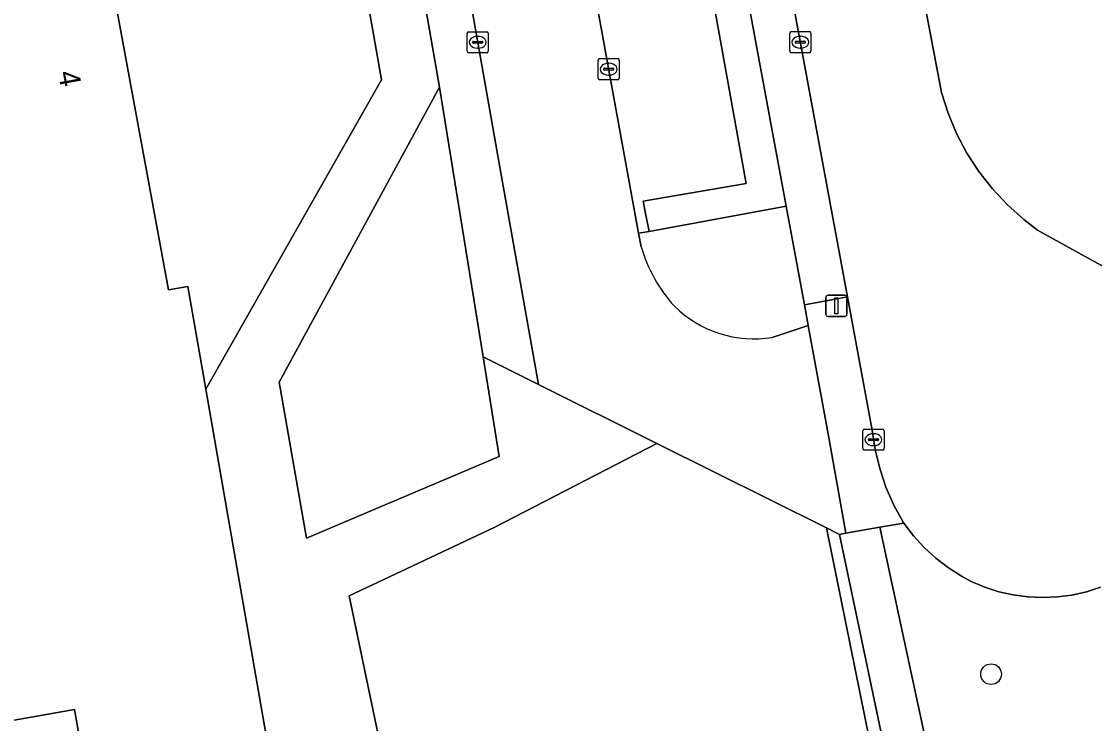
# Model space of a CAD drawing. Extents: x 159451 to 160664, y 388402 to 389723.
# Drawn here: x 159647.4 to 159698.3, y 388842.8 to 388876 of the extents above; entities that cross this region are included whole.
import ezdxf

# ---------------------------------------------------------------- set-up
doc = ezdxf.new("R2010")
doc.units = 0
for name, color, linetype in [('IMGEO_Boom', 7, 'Continuous'), ('IMGEO_Erf', 7, 'Continuous'), ('IMGEO_Groenvoorziening', 7, 'Continuous'), ('IMGEO_Hek', 7, 'Continuous'), ('IMGEO_Kolk', 7, 'Continuous'), ('IMGEO_Lichtmast', 7, 'Continuous'), ('IMGEO_Loofbos', 7, 'Continuous'), ('IMGEO_Muur', 7, 'Continuous'), ('IMGEO_Pand', 7, 'Continuous'), ('IMGEO_Pand_nummerreeks', 7, 'Continuous'), ('IMGEO_Parkeervlak_open', 7, 'Continuous'), ('IMGEO_Rijbaan_lokaal_open', 7, 'Continuous'), ('IMGEO_Voetpad_halfverhard', 7, 'Continuous'), ('IMGEO_Voetpad_open', 7, 'Continuous')]:
    doc.layers.add(name, color=color, linetype=linetype)

msp = doc.modelspace()

# ---------------------------------------------------------------- linework, layer by layer
at = {"layer": 'IMGEO_Boom'}
msp.add_circle((159693.409, 388845.115), 0.489, dxfattribs=at)
at = {"layer": 'IMGEO_Erf'}
msp.add_lwpolyline([(159656.968, 388916.294), (159649.385, 388920.318), (159651.233, 388910.205), (159650.908, 388910.146), (159653.635, 388895.213), (159653.68, 388894.967), (159656.268, 388895.439), (159657.177, 388890.462), (159654.589, 388889.989), (159654.634, 388889.743), (159655.416, 388885.464), (159650.497, 388884.566), (159654.41, 388863.313), (159655.341, 388863.475), (159656.187, 388858.62), (159664.511, 388873.264), (159661.405, 388890.98), (159660.445, 388896.457)], close=True, dxfattribs=at)
msp.add_lwpolyline([(159688.561, 388837.482), (159685.613, 388852.043), (159677.571, 388856.044), (159669.854, 388852.057), (159662.982, 388848.818), (159665.856, 388835.05)], dxfattribs=at)
at = {"layer": 'IMGEO_Groenvoorziening'}
msp.add_lwpolyline([(159667.257, 388872.925), (159659.66, 388858.946), (159660.961, 388851.556), (159670.093, 388855.423), (159669.328, 388860.143)], close=True, dxfattribs=at)
for points in [[(159683.694, 388867.275), (159677.206, 388866.087), (159676.699, 388866.003), (159676.818, 388865.36)], [(159683.026, 388861.066), (159684.739, 388861.634), (159684.558, 388862.613), (159683.694, 388867.275)]]:
    msp.add_lwpolyline(points, dxfattribs=at)
for centre, radius, start, end in [((159683.924, 388867.487), 7.417, 196.6614, 221.8301), ((159682.183, 388866.425), 5.425, 225.7386, 278.9356)]:
    msp.add_arc(centre, radius, start, end, dxfattribs=at)
at = {"layer": 'IMGEO_Hek'}
msp.add_lwpolyline([(159685.613, 388852.043), (159688.561, 388837.482)], dxfattribs=at)
at = {"layer": 'IMGEO_Kolk'}
for p, q in [((159668.576, 388874.619), (159668.576, 388875.471)), ((159668.651, 388875.545), (159669.503, 388875.545)), ((159669.064, 388875.325), (159669.089, 388875.325)), ((159669.577, 388875.471), (159669.577, 388874.619)), ((159683.867, 388874.624), (159683.867, 388875.476)), ((159683.942, 388875.55), (159684.794, 388875.55)), ((159684.355, 388875.33), (159684.38, 388875.33)), ((159684.868, 388875.476), (159684.868, 388874.624)), ((159668.835, 388875.039), (159668.835, 388875.051)), ((159669.273, 388875.002), (159668.875, 388875.002)), ((159668.878, 388875.088), (159669.276, 388875.088)), ((159669.319, 388875.051), (159669.319, 388875.039)), ((159684.126, 388875.044), (159684.126, 388875.056)), ((159684.564, 388875.007), (159684.166, 388875.007)), ((159684.169, 388875.093), (159684.567, 388875.093)), ((159684.61, 388875.056), (159684.61, 388875.044)), ((159669.503, 388874.545), (159668.651, 388874.545)), ((159669.087, 388874.765), (159669.062, 388874.765)), ((159684.794, 388874.55), (159683.942, 388874.55)), ((159684.378, 388874.77), (159684.353, 388874.77)), ((159674.782, 388873.345), (159674.782, 388874.197)), ((159674.857, 388874.271), (159675.709, 388874.271)), ((159675.041, 388873.765), (159675.041, 388873.777)), ((159675.084, 388873.814), (159675.482, 388873.814)), ((159675.27, 388874.051), (159675.295, 388874.051)), ((159675.525, 388873.777), (159675.525, 388873.765)), ((159675.783, 388874.197), (159675.783, 388873.345)), ((159675.709, 388873.271), (159674.857, 388873.271)), ((159675.479, 388873.728), (159675.081, 388873.728)), ((159675.293, 388873.491), (159675.268, 388873.491)), ((159687.332, 388855.796), (159687.332, 388856.648)), ((159687.407, 388856.722), (159688.259, 388856.722)), ((159687.82, 388856.502), (159687.845, 388856.502)), ((159688.333, 388856.648), (159688.333, 388855.796)), ((159687.591, 388856.216), (159687.591, 388856.228)), ((159688.029, 388856.179), (159687.631, 388856.179)), ((159687.634, 388856.265), (159688.032, 388856.265)), ((159688.075, 388856.228), (159688.075, 388856.216)), ((159688.259, 388855.722), (159687.407, 388855.722)), ((159687.843, 388855.942), (159687.818, 388855.942))]:
    msp.add_line(p, q, dxfattribs=at)
for points in [[(159668.576, 388874.619), (159668.576, 388875.471)], [(159668.651, 388875.545), (159669.503, 388875.545)], [(159669.577, 388875.471), (159669.577, 388874.619)], [(159683.867, 388874.624), (159683.867, 388875.476)], [(159683.942, 388875.55), (159684.794, 388875.55)], [(159684.868, 388875.476), (159684.868, 388874.624)], [(159669.503, 388874.545), (159668.651, 388874.545)], [(159684.794, 388874.55), (159683.942, 388874.55)], [(159674.782, 388873.345), (159674.782, 388874.197)], [(159674.857, 388874.271), (159675.709, 388874.271)], [(159675.783, 388874.197), (159675.783, 388873.345)], [(159675.709, 388873.271), (159674.857, 388873.271)], [(159687.332, 388855.796), (159687.332, 388856.648)], [(159687.407, 388856.722), (159688.259, 388856.722)], [(159688.333, 388856.648), (159688.333, 388855.796)], [(159688.259, 388855.722), (159687.407, 388855.722)]]:
    msp.add_lwpolyline(points, dxfattribs=at)
for centre, radius, start, end in [((159668.653, 388875.469), 0.0765, 91.552, 178.448), ((159668.653, 388875.469), 0.0765, 91.552, 178.448), ((159669.501, 388875.469), 0.0765, 1.552, 88.448), ((159669.501, 388875.469), 0.0765, 1.552, 88.448), ((159683.944, 388875.474), 0.0765, 91.552, 178.448), ((159683.944, 388875.474), 0.0765, 91.552, 178.448), ((159684.792, 388875.474), 0.0765, 1.552, 88.448), ((159684.792, 388875.474), 0.0765, 1.552, 88.448), ((159668.875, 388875.048), 0.0403, 85.8775, 175.7526), ((159668.872, 388875.038), 0.0366, 178.938, 274.7102), ((159669.276, 388875.045), 0.043, 264.8664, 352.4533), ((159669.28, 388875.05), 0.0386, 1.7309, 96.639), ((159684.166, 388875.053), 0.0403, 85.8775, 175.7526), ((159684.163, 388875.043), 0.0366, 178.938, 274.7102), ((159684.567, 388875.05), 0.043, 264.8664, 352.4533), ((159684.571, 388875.055), 0.0386, 1.7309, 96.639), ((159668.653, 388874.621), 0.0765, 181.552, 268.448), ((159668.653, 388874.621), 0.0765, 181.552, 268.448), ((159669.501, 388874.621), 0.0765, 271.552, 358.448), ((159669.501, 388874.621), 0.0765, 271.552, 358.448), ((159683.944, 388874.626), 0.0765, 181.552, 268.448), ((159683.944, 388874.626), 0.0765, 181.552, 268.448), ((159684.792, 388874.626), 0.0765, 271.552, 358.448), ((159684.792, 388874.626), 0.0765, 271.552, 358.448), ((159674.859, 388874.195), 0.0765, 91.552, 178.448), ((159674.859, 388874.195), 0.0765, 91.552, 178.448), ((159675.081, 388873.774), 0.0403, 85.8775, 175.7526), ((159675.486, 388873.776), 0.0386, 1.7309, 96.639), ((159675.707, 388874.195), 0.0765, 1.552, 88.448), ((159675.707, 388874.195), 0.0765, 1.552, 88.448), ((159674.859, 388873.347), 0.0765, 181.552, 268.448), ((159674.859, 388873.347), 0.0765, 181.552, 268.448), ((159675.078, 388873.764), 0.0366, 178.938, 274.7102), ((159675.482, 388873.771), 0.043, 264.8664, 352.4533), ((159675.707, 388873.347), 0.0765, 271.552, 358.448), ((159675.707, 388873.347), 0.0765, 271.552, 358.448), ((159687.409, 388856.646), 0.0765, 91.552, 178.448), ((159687.409, 388856.646), 0.0765, 91.552, 178.448), ((159688.257, 388856.646), 0.0765, 1.552, 88.448), ((159688.257, 388856.646), 0.0765, 1.552, 88.448), ((159687.631, 388856.225), 0.0403, 85.8775, 175.7526), ((159687.628, 388856.215), 0.0366, 178.938, 274.7102), ((159688.032, 388856.222), 0.043, 264.8664, 352.4533), ((159688.036, 388856.227), 0.0386, 1.7309, 96.639), ((159687.409, 388855.798), 0.0765, 181.552, 268.448), ((159687.409, 388855.798), 0.0765, 181.552, 268.448), ((159688.257, 388855.798), 0.0765, 271.552, 358.448), ((159688.257, 388855.798), 0.0765, 271.552, 358.448)]:
    msp.add_arc(centre, radius, start, end, dxfattribs=at)
for centre, major_axis, ratio, start_param, end_param in [((159669.063, 388875.045), (-0.387, 0.002), 0.722429, 4.712389, 7.853982), ((159669.088, 388875.045), (-0.39, 0.002), 0.717154, 1.570796, 4.712389), ((159684.354, 388875.05), (-0.387, 0.002), 0.722429, 4.712389, 7.853982), ((159684.379, 388875.05), (-0.39, 0.002), 0.717154, 1.570796, 4.712389), ((159675.269, 388873.771), (-0.387, 0.002), 0.722429, 4.712389, 7.853982), ((159675.294, 388873.771), (-0.39, 0.002), 0.717154, 1.570796, 4.712389), ((159687.819, 388856.222), (-0.387, 0.002), 0.722429, 4.712389, 7.853982), ((159687.844, 388856.222), (-0.39, 0.002), 0.717154, 1.570796, 4.712389)]:
    msp.add_ellipse(centre, major_axis=major_axis, ratio=ratio, start_param=start_param, end_param=end_param, dxfattribs=at)
at = {"layer": 'IMGEO_Lichtmast'}
for p, q in [((159685.582, 388862.159), (159685.582, 388862.959)), ((159685.582, 388862.959), (159685.582, 388862.159)), ((159685.682, 388863.059), (159686.472, 388863.059)), ((159686.472, 388863.059), (159685.682, 388863.059)), ((159686.572, 388862.959), (159686.572, 388862.159)), ((159686.572, 388862.159), (159686.572, 388862.959)), ((159686.472, 388862.059), (159685.682, 388862.059)), ((159685.682, 388862.059), (159686.472, 388862.059))]:
    msp.add_line(p, q, dxfattribs=at)
msp.add_lwpolyline([(159686.002, 388862.934), (159686.152, 388862.934), (159686.152, 388862.184), (159686.002, 388862.184), (159686.002, 388862.934)], dxfattribs=at)
for centre, start, end in [((159685.682, 388862.959), 90, 180), ((159685.682, 388862.959), 90, 180), ((159686.472, 388862.959), 0, 90), ((159686.472, 388862.959), 360, 90), ((159685.682, 388862.159), 180, 270), ((159685.682, 388862.159), 180, 270), ((159686.472, 388862.159), 270, 0), ((159686.472, 388862.159), 270, 0)]:
    msp.add_arc(centre, 0.1, start, end, dxfattribs=at)
at = {"layer": 'IMGEO_Loofbos'}
for points in [[(159683.633, 388912.346), (159686.514, 388896.65), (159691.063, 388872.674), (159691.376, 388871.68), (159691.776, 388870.719), (159692.261, 388869.796), (159692.827, 388868.921), (159693.468, 388868.1), (159694.18, 388867.339), (159694.957, 388866.645), (159695.614, 388866.147), (159699.217, 388864.155)], [(159666.766, 388725.317), (159672.123, 388750), (159679.188, 388782.55), (159690.146, 388833.037), (159689.111, 388837.976), (159686.229, 388851.737), (159685.613, 388852.043), (159688.561, 388837.482), (159689.421, 388833.236), (159678.25, 388782.74), (159562.528, 388756.756), (159538.553, 388875.669)], [(159698.59, 388849.232), (159697.925, 388849.017), (159697.243, 388848.863), (159696.55, 388848.77), (159695.851, 388848.739), (159695.153, 388848.771), (159694.46, 388848.865), (159693.778, 388849.021), (159693.113, 388849.237), (159692.47, 388849.511), (159692.038, 388849.741), (159691.398, 388850.144), (159690.797, 388850.603), (159690.239, 388851.114), (159689.729, 388851.673), (159689.271, 388852.275), (159688.139, 388852.075), (159690.83, 388839.519)]]:
    msp.add_lwpolyline(points, dxfattribs=at)
at = {"layer": 'IMGEO_Muur'}
msp.add_lwpolyline([(159681.068, 388881.449), (159678.498, 388895.409), (159674.961, 388894.751), (159672.023, 388894.206), (159672.355, 388892.368), (159677.318, 388893.266), (159681.802, 388868.361), (159676.915, 388867.519), (159677.034, 388866.93), (159677.206, 388866.087), (159683.694, 388867.275)], close=True, dxfattribs=at)
at = {"layer": 'IMGEO_Pand'}
for points in [[(159659.172, 388841.486), (159656.187, 388858.62), (159655.341, 388863.475), (159654.41, 388863.313), (159650.497, 388884.566), (159655.416, 388885.464), (159654.634, 388889.743), (159654.589, 388889.989), (159657.177, 388890.462), (159656.268, 388895.439), (159653.68, 388894.967), (159653.635, 388895.213), (159650.908, 388910.146), (159651.233, 388910.205), (159649.385, 388920.318), (159647.084, 388919.897)], [(159645.57, 388842.67), (159649.961, 388843.435), (159650.562, 388839.986)]]:
    msp.add_lwpolyline(points, dxfattribs=at)
at = {"layer": 'IMGEO_Parkeervlak_open'}
for points in [[(159677.318, 388893.266), (159672.355, 388892.368), (159672.023, 388894.206), (159671.575, 388894.125), (159676.699, 388866.003), (159677.206, 388866.087), (159677.034, 388866.93), (159676.915, 388867.519), (159681.802, 388868.361)], [(159666.75, 388888.181), (159666.095, 388891.836), (159666.069, 388891.98), (159663.993, 388891.631), (159667.257, 388872.925), (159669.328, 388860.143), (159671.949, 388858.84), (159670.127, 388869.124)]]:
    msp.add_lwpolyline(points, close=True, dxfattribs=at)
at = {"layer": 'IMGEO_Rijbaan_lokaal_open'}
for points in [[(159699.217, 388864.155), (159695.614, 388866.147), (159694.957, 388866.645), (159694.18, 388867.339), (159693.468, 388868.1), (159692.827, 388868.921), (159692.261, 388869.796), (159691.776, 388870.719), (159691.376, 388871.68), (159691.063, 388872.674), (159686.514, 388896.65), (159683.633, 388912.346), (159681.485, 388924.154), (159681.28, 388925.163), (159674.135, 388964.086)], [(159669.579, 388916.245), (159673.112, 388918.89), (159674.043, 388919.607), (159672.732, 388926.753), (159661.539, 388917.368), (159663.341, 388907.198), (159665.114, 388897.31), (159666.069, 388891.98), (159666.095, 388891.836), (159666.75, 388888.181), (159670.127, 388869.124), (159671.949, 388858.84), (159677.571, 388856.044), (159685.613, 388852.043), (159686.229, 388851.737), (159686.526, 388851.79), (159685.74, 388856.234), (159684.739, 388861.634), (159683.026, 388861.066)], [(159676.123, 388919.495), (159686.606, 388862.993), (159687.778, 388856.678), (159687.913, 388855.759), (159688.13, 388854.856), (159688.426, 388853.975), (159688.8, 388853.125), (159689.249, 388852.311), (159689.271, 388852.275), (159689.729, 388851.673), (159690.239, 388851.114), (159690.797, 388850.603), (159691.398, 388850.144), (159692.038, 388849.741), (159692.47, 388849.511), (159693.113, 388849.237), (159693.778, 388849.021), (159694.46, 388848.865), (159695.153, 388848.771), (159695.851, 388848.739), (159696.55, 388848.77), (159697.243, 388848.863), (159697.925, 388849.017), (159698.59, 388849.232)], [(159676.818, 388865.36), (159676.699, 388866.003), (159671.575, 388894.125), (159671.044, 388897.036), (159670.805, 388898.349), (159668.295, 388912.128), (159668.207, 388912.611)]]:
    msp.add_lwpolyline(points, dxfattribs=at)
for centre, radius, start, end in [((159683.924, 388867.487), 7.417, 196.6614, 221.8301), ((159682.183, 388866.425), 5.425, 225.7386, 278.9356)]:
    msp.add_arc(centre, radius, start, end, dxfattribs=at)
at = {"layer": 'IMGEO_Voetpad_halfverhard'}
msp.add_lwpolyline([(159690.025, 388823.116), (159690.927, 388827.247), (159691.922, 388831.802), (159692.206, 388833.101), (159690.83, 388839.519), (159688.139, 388852.075), (159686.526, 388851.79), (159686.229, 388851.737), (159689.111, 388837.976), (159690.146, 388833.037), (159679.188, 388782.55), (159672.123, 388750), (159666.766, 388725.317)], dxfattribs=at)
at = {"layer": 'IMGEO_Voetpad_open'}
for points in [[(159665.856, 388835.05), (159662.982, 388848.818), (159669.854, 388852.057), (159677.571, 388856.044), (159671.949, 388858.84), (159669.328, 388860.143), (159670.093, 388855.423), (159660.961, 388851.556), (159659.66, 388858.946), (159667.257, 388872.925), (159663.993, 388891.631), (159666.069, 388891.98), (159665.114, 388897.31), (159663.007, 388896.85), (159662.479, 388899.798), (159659.598, 388915.741), (159661.539, 388917.368), (159672.732, 388926.753), (159672.283, 388929.255), (159672.185, 388929.801), (159659.557, 388918.986), (159649.975, 388924.443), (159611.805, 388918.556)], [(159647.084, 388919.897), (159649.385, 388920.318), (159656.968, 388916.294), (159660.445, 388896.457), (159661.405, 388890.98), (159664.511, 388873.264), (159656.187, 388858.62), (159659.172, 388841.486)], [(159650.562, 388839.986), (159649.961, 388843.435), (159645.57, 388842.67)]]:
    msp.add_lwpolyline(points, dxfattribs=at)
for points in [[(159676.123, 388919.495), (159674.131, 388919.128), (159675.197, 388913.339), (159677.97, 388898.274), (159678.498, 388895.409), (159681.068, 388881.449), (159683.694, 388867.275), (159684.558, 388862.613), (159686.606, 388862.993)], [(159684.558, 388862.613), (159684.739, 388861.634), (159685.74, 388856.234), (159686.526, 388851.79), (159688.139, 388852.075), (159689.271, 388852.275), (159689.249, 388852.311), (159688.8, 388853.125), (159688.426, 388853.975), (159688.13, 388854.856), (159687.913, 388855.759), (159687.778, 388856.678), (159686.606, 388862.993)]]:
    msp.add_lwpolyline(points, close=True, dxfattribs=at)

# ---------------------------------------------------------------- texts
at = {"layer": 'IMGEO_Pand_nummerreeks'}
msp.add_text('4', height=1, rotation=280.4322, dxfattribs=at).set_placement((159649.179, 388873.613))

doc.saveas('drawing.dxf')
